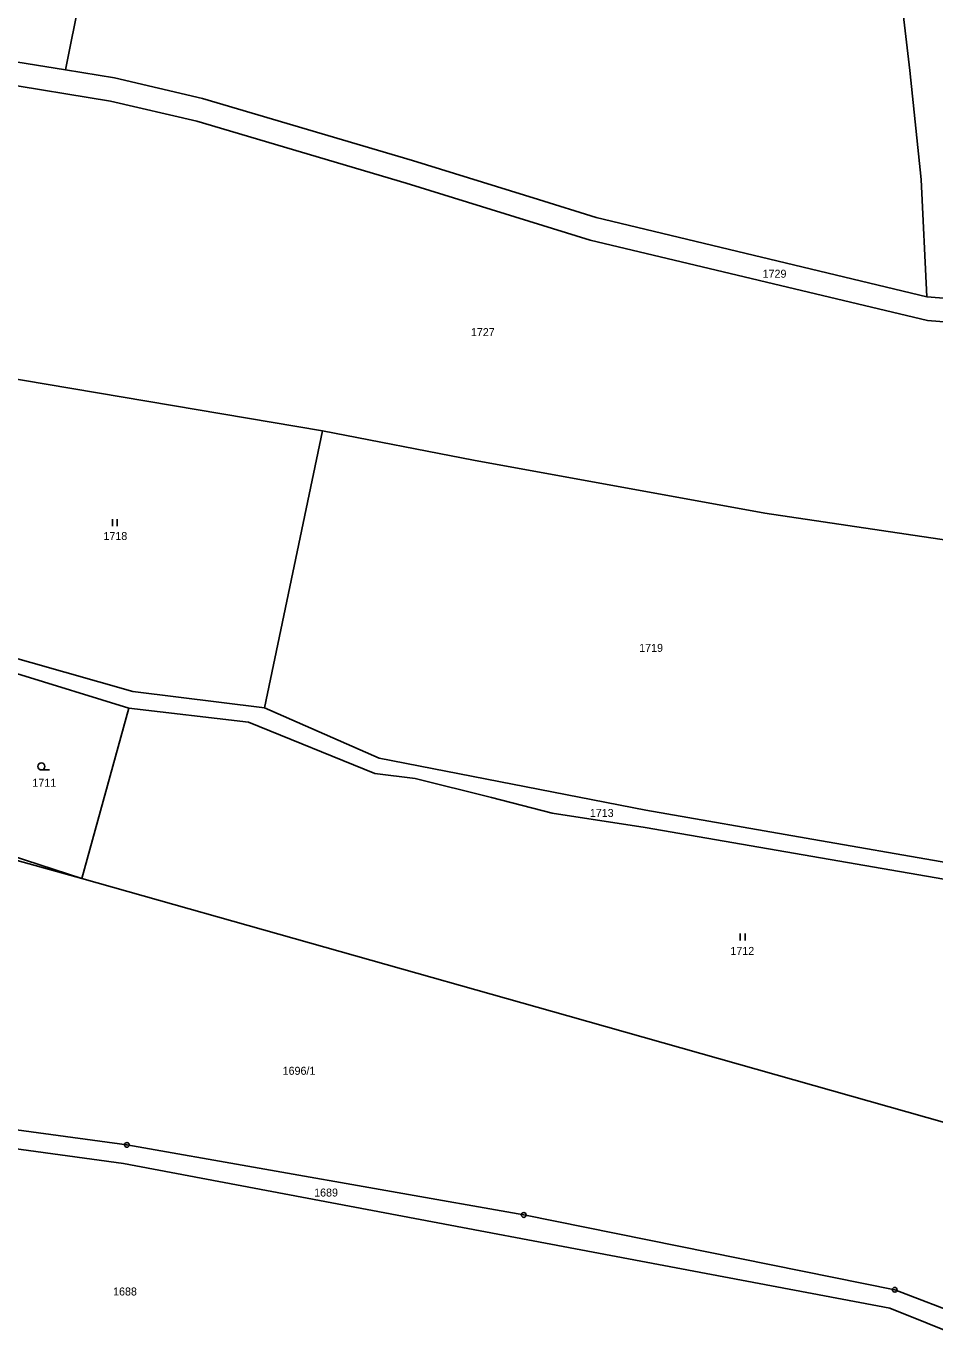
# Model space of a CAD drawing. Extents: x -601131 to -597152, y -1058536 to -1055911.
# Drawn here: x -599259.4 to -599066.3, y -1057555.3 to -1057278.4 of the extents above; entities that cross this region are included whole.
import ezdxf
from ezdxf.enums import TextEntityAlignment as Align

# ---------------------------------------------------------------- set-up
doc = ezdxf.new("R2010")
doc.units = 0
doc.header["$LTSCALE"] = 0.68
for name, color, linetype, lineweight in [('1', 7, 'Continuous', 25), ('3', 7, 'Continuous', 25), ('8', 7, 'Continuous', 25)]:
    doc.layers.add(name, color=color, linetype=linetype, lineweight=lineweight)
doc.layers.add('2', color=7, linetype='Continuous')

msp = doc.modelspace()

# ---------------------------------------------------------------- linework, layer by layer
at = {"layer": '1'}
for p, q in [((-599251, -1057287.69), (-599244.72, -1057256.29)), ((-599071.62, -1057287.83), (-599074.47, -1057263.35)), ((-599251, -1057287.69), (-599276.23, -1057283.57)), ((-599241.43, -1057294.32), (-599276.95, -1057288.52)), ((-599240.58, -1057289.39), (-599251, -1057287.69)), ((-599221.89, -1057293.71), (-599240.58, -1057289.39)), ((-599069.18, -1057310.97), (-599071.62, -1057287.83)), ((-599223.12, -1057298.56), (-599241.43, -1057294.32)), ((-599177.28, -1057306.89), (-599221.89, -1057293.71)), ((-599178.61, -1057311.71), (-599223.12, -1057298.56)), ((-599150.48, -1057315.19), (-599177.28, -1057306.89)), ((-599139.53, -1057323.81), (-599178.61, -1057311.71)), ((-599067.99, -1057335.85), (-599069.18, -1057310.97)), ((-599138.23, -1057318.99), (-599150.48, -1057315.19)), ((-599067.99, -1057335.85), (-599138.23, -1057318.99)), ((-599067.87, -1057340.91), (-599139.53, -1057323.81)), ((-599044.73, -1057337.81), (-599067.99, -1057335.85)), ((-599044.53, -1057342.86), (-599067.87, -1057340.91)), ((-599267.5, -1057352.34), (-599196.38, -1057364.38)), ((-599196.38, -1057364.38), (-599208.71, -1057423.21)), ((-599196.38, -1057364.38), (-599164.31, -1057370.61)), ((-599164.31, -1057370.61), (-599102.38, -1057381.87)), ((-599102.38, -1057381.87), (-599042.15, -1057390.77)), ((-599236.7, -1057419.73), (-599294.92, -1057403.13)), ((-599261.4, -1057415.87), (-599237.59, -1057423.29)), ((-599208.71, -1057423.21), (-599236.7, -1057419.73)), ((-599237.59, -1057423.29), (-599247.53, -1057459.44)), ((-599237.59, -1057423.29), (-599212.15, -1057426.23)), ((-599184.33, -1057433.88), (-599208.71, -1057423.21)), ((-599212.15, -1057426.23), (-599185.28, -1057437.11)), ((-599127.72, -1057444.9), (-599184.33, -1057433.88)), ((-599185.28, -1057437.11), (-599176.7, -1057438.2)), ((-599176.7, -1057438.2), (-599160.47, -1057442.22)), ((-599160.47, -1057442.22), (-599147.57, -1057445.6)), ((-599299.66, -1057444.95), (-599247.53, -1057459.44)), ((-599093.62, -1057450.91), (-599127.72, -1057444.9)), ((-599147.57, -1057445.6), (-599127.83, -1057448.58)), ((-599247.53, -1057459.44), (-599274.58, -1057450.67)), ((-599127.83, -1057448.58), (-599064.38, -1057459.58)), ((-599063.5, -1057456.12), (-599093.62, -1057450.91)), ((-599144.3, -1057488.64), (-599247.53, -1057459.44)), ((-599041.08, -1057517.85), (-599144.3, -1057488.64)), ((-599314.99, -1057505.64), (-599237.96, -1057516.04)), ((-599238.7, -1057519.97), (-599315.77, -1057509.56)), ((-599237.96, -1057516.04), (-599153.63, -1057530.93)), ((-599075.83, -1057550.69), (-599238.7, -1057519.97)), ((-599153.63, -1057530.93), (-599074.8, -1057546.82)), ((-599074.8, -1057546.82), (-599054.2, -1057554.72)), ((-599054.42, -1057559.4), (-599075.83, -1057550.69))]:
    msp.add_line(p, q, dxfattribs=at)
at = {"layer": '3'}
for p, q in [((-599241.031, -1057384.6), (-599241.031, -1057383.1)), ((-599240.03, -1057384.6), (-599240.03, -1057383.1)), ((-599256.133, -1057436.39), (-599254.383, -1057436.39)), ((-599107.621, -1057472.6), (-599107.621, -1057471.1)), ((-599106.62, -1057472.6), (-599106.62, -1057471.1))]:
    msp.add_line(p, q, dxfattribs=at)
msp.add_circle((-599256.1329, -1057435.6398), 0.75, dxfattribs=at)
at = {"layer": '8'}
for centre, radius in [((-599237.96, -1057516.0399), 0.5), ((-599237.96, -1057516.0399), 0.0303), ((-599153.63, -1057530.9299), 0.5), ((-599153.63, -1057530.9299), 0.0303), ((-599074.8, -1057546.8199), 0.5), ((-599074.8, -1057546.8199), 0.0303)]:
    msp.add_circle(centre, radius, dxfattribs=at)

# ---------------------------------------------------------------- texts
at = {"layer": '2'}
for s, p in [('1729', (-599100.35, -1057331.822)), ('1727', (-599162.34, -1057344.232)), ('1718', (-599240.42, -1057387.542)), ('1719', (-599126.58, -1057411.302)), ('1711', (-599255.53, -1057439.962)), ('1713', (-599137.07, -1057446.372)), ('1712', (-599107.2, -1057475.682)), ('1689', (-599195.65, -1057527.012)), ('1688', (-599238.37, -1057548.032))]:
    msp.add_text(s, height=1.7, dxfattribs=at).set_placement(p, align=Align.CENTER)
msp.add_text('1696/1', height=1.7, dxfattribs=at).set_placement((-599204.87, -1057501.145))

doc.saveas('drawing.dxf')
